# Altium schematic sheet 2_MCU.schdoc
size 307 x 218 mm; Symbol: Artery_A4; Device: Artery_A4; @Project Name: AT-START-M416; @Page Count: 4; @Create Date: 2024-11-11; Company: Artery Technology; Drawed: SD; Version: 1.1; Page Size: A4; @Update Date: 2024-11-14; @Page No: 2; @Schematic Name: AT-START-M416-V1.1; @Page Name: MCU; Title Block Position: 3; Width: 1170; Height: 825; Region Start: 1; X Region Count: 6; Y Region Count: 4; Blade Width: 10; @Board Name: AT-START-M416-V1.1; @Create Time: 14:16:05; @Update Time: 13:53:32
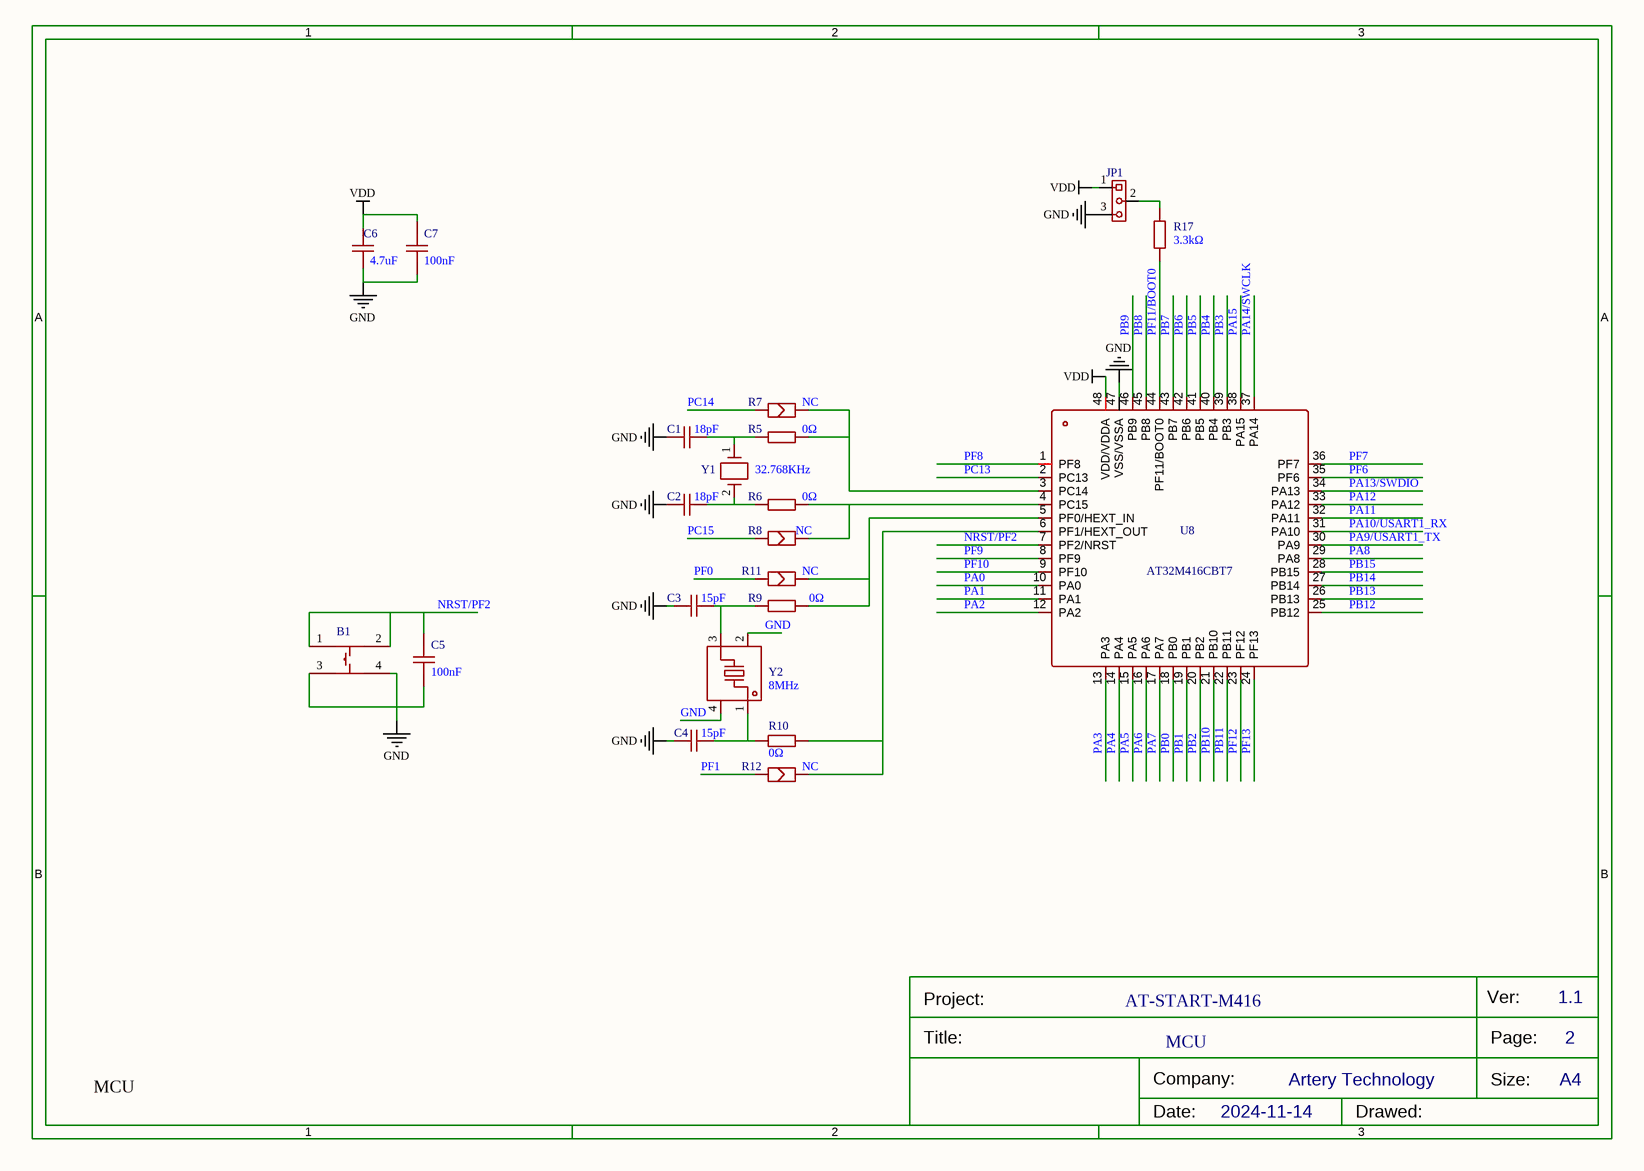
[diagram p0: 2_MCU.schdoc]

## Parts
B1  TS-1002S-05026C  [KEY-SMD_4P-L6.0-W6.0-P4.50-LS9.0]  (value not drawn)
C1  18pF  [C0603]
C2  18pF  [C0603]
C3  15pF  [C0603]
C4  15pF  [C0603]
C5  100nF  [C0603]
C6  4.7uF  [C0603]
C7  100nF  [C0603]
JP1  2.54-1*3P针  [HDR-TH_3P-P2.54-V-M-1]  (value not drawn)
R5  0Ω  [SB-PAD_2]
R6  0Ω  [SB-PAD_2]
R7  NC  [SB-PAD_2]
R8  NC  [SB-PAD_2]
R9  0Ω  [SB-PAD_2]
R10  0Ω  [SB-PAD_2]
R11  NC  [SB-PAD_2]
R12  NC  [SB-PAD_2]
R17  3.3kΩ  [R0603]
U8  (no value)  [LQFP-48_L7.0-W7.0-P0.50-LS9.0-BL]
Y1  32.768KHz  [XTAL_SOP - FC-12M]
Y2  8MHz  [CRYSTAL-SMD_4P-L3.2-W2.5-BL]

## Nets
GND: B1.3 B1.4 C1.1 C2.1 C3.1 C4.1 C5.1 C6.1 C7.1 JP1.3 U8.47(VSS/VSSA) Y2.2(GND) Y2.4(GND)
VDD: C6.2 C7.2 JP1.1 U8.48(VDD/VDDA)
NRST/PF2: B1.1 B1.2 C5.2 U8.7(PF2/NRST)
PA0: U8.10(PA0)
PA1: U8.11(PA1)
PA2: U8.12(PA2)
PA3: U8.13(PA3)
PA4: U8.14(PA4)
PA5: U8.15(PA5)
PA6: U8.16(PA6)
PA7: U8.17(PA7)
PA8: U8.29(PA8)
PA9/USART1_TX: U8.30(PA9)
PA10/USART1_RX: U8.31(PA10)
PA11: U8.32(PA11)
PA12: U8.33(PA12)
PA13/SWDIO: U8.34(PA13)
PA14/SWCLK: U8.37(PA14)
PA15: U8.38(PA15)
PB0: U8.18(PB0)
PB1: U8.19(PB1)
PB2: U8.20(PB2)
PB3: U8.39(PB3)
PB4: U8.40(PB4)
PB5: U8.41(PB5)
PB6: U8.42(PB6)
PB7: U8.43(PB7)
PB8: U8.45(PB8)
PB9: U8.46(PB9)
PB10: U8.21(PB10)
PB11: U8.22(PB11)
PB12: U8.25(PB12)
PB13: U8.26(PB13)
PB14: U8.27(PB14)
PB15: U8.28(PB15)
PC13: U8.2(PC13)
PC14: R7.1
PC15: R8.1
PF0: R11.1
PF1: R12.1
PF6: U8.35(PF6)
PF7: U8.36(PF7)
PF8: U8.1(PF8)
PF9: U8.8(PF9)
PF10: U8.9(PF10)
PF11/BOOT0: R17.1 U8.44(PF11/BOOT0)
PF12: U8.23(PF12)
PF13: U8.24(PF13)
NetC1_2: C1.2 R5.1 Y1.1
NetC2_2: C2.2 R6.1 Y1.2
NetC3_2: C3.2 R9.1 Y2.3
NetC4_2: C4.2 R10.1 Y2.1
NetJP1_2: JP1.2 R17.2
NetR5_2: R5.2 R7.2 U8.3(PC14)
NetR6_2: R6.2 R8.2 U8.4(PC15)
NetR9_2: R9.2 R11.2 U8.5(PF0/HEXT_IN)
NetR10_2: R10.2 R12.2 U8.6(PF1/HEXT_OUT)

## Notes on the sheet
- (near U8) AT32M416CBT7
- AT-START-M416
- MCU

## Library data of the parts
B1 = TS-1002S-05026C: Manufacturer: XUNPU(讯普); Add into BOM: yes; Circuit: 单刀单掷; Actuator Style: 圆形按钮; Switch Length: 6mm; Switch Height: 5mm; Contact Current: 50mA; Voltage Rating (DC): 12V; Origin Footprint: KEY_SOP_6*6
C1 C2 = CL10C180JB8NNNC: Manufacturer: SAMSUNG(三星); Add into BOM: yes; Tolerance: ±5%; Voltage Rated: 50V; Temperature Coefficient: C0G
C3 C4 = CL10C150JB8NNNC: Manufacturer: SAMSUNG(三星); Add into BOM: yes; Tolerance: ±5%; Voltage Rated: 50V; Temperature Coefficient: C0G
C5 C7 = CC0603KRX7R9BB104: Manufacturer: YAGEO(国巨); Add into BOM: yes; Tolerance: ±10%; Voltage Rated: 50V; Temperature Coefficient: X7R
C6 = CL10A475KO8NNNC: Manufacturer: SAMSUNG(三星); Add into BOM: yes; Tolerance: ±10%; Voltage Rated: 16V; Temperature Coefficient: X5R
JP1 = 2.54-1*3P针: Manufacturer: BOOMELE(博穆精密); Symbol: Header-Male-2.54_1x3; Add into BOM: yes; Pin Structure: 1x3P; Pitch: 2.54mm; Circluar Pins/Square Pins: 方针; Current Rating (Max): 3A; Origin Footprint: HEADER 1X2
R5 R6 R9 R10 = 0603WAF0000T5E: Manufacturer: UNI-ROYAL(厚声); Add into BOM: yes; Tolerance: ±1%; Power(Watts): 100mW; Overload Voltage (Max): 75V; Origin Footprint: SB-PAD
R7 R8 R11 R12 = SB_PAD: Symbol: SB-PAD; Convert to PCB: yes
R17 = 0603WAF3301T5E: Manufacturer: UNI-ROYAL(厚声); Symbol: 0603WAF1002T5E; Add into BOM: yes; Tolerance: ±1%; Power(Watts): 100mW; Overload Voltage (Max): 75V; Temperature Coefficient: ±100ppm/℃
U8 = AT32M412CxT7: Manufacturer: ArteryTechnology; Add into BOM: yes
Y1 = 32.768KHz: Symbol: 32.768KHz,CRY,30PPM,Size_3X8; Add into BOM: yes
Y2 = CJ13-080001210B20: Manufacturer: CJ(江苏长电/长晶); Add into BOM: yes; Normal temperature Frequency Tolerance: ±10ppm; External load capacitor: 12pF; Crystal Type: 贴片晶振; Frequency Stability(Full temperature range): ±30ppm; Equivalent Series Resistance (ESR): 100Ω; Origin Footprint: SMD_5032_4P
